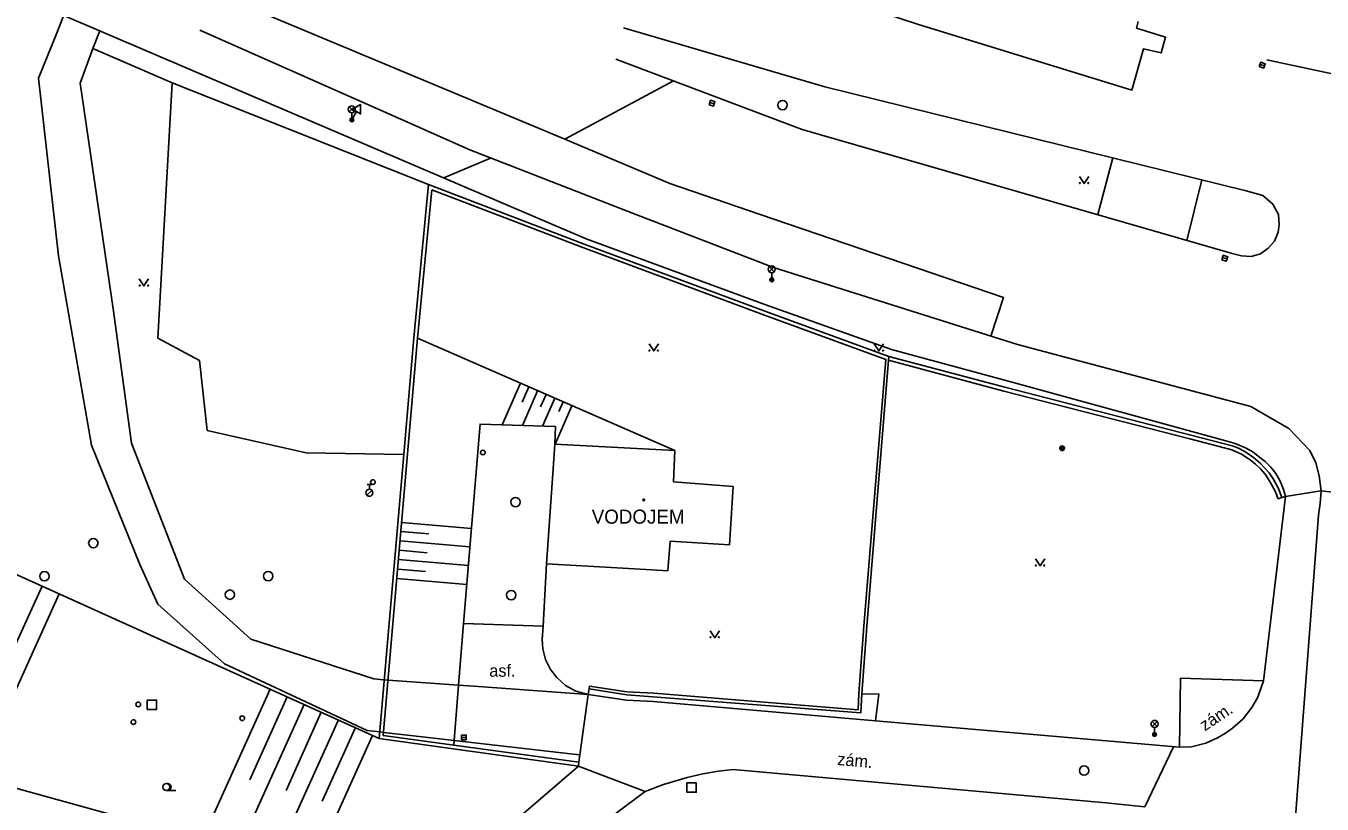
# Model space of a CAD drawing. Extents: x -602419 to -601554, y -1162937 to -1162362.
# Drawn here: x -602032.9 to -601963.7, y -1162448.9 to -1162407.3 of the extents above; entities that cross this region are included whole.
import ezdxf

# ---------------------------------------------------------------- set-up
doc = ezdxf.new("R2010")
doc.units = 0
doc.layers.add('Podklad', color=7, linetype='Continuous')

msp = doc.modelspace()

# ---------------------------------------------------------------- linework, layer by layer
at = {"layer": 'Podklad'}
for p, q in [((-601966.9783, -1162409.3796), (-601966.7417, -1162409.4604)), ((-602015.6024, -1162411.91), (-602015.3374, -1162411.645)), ((-602015.6024, -1162411.645), (-602015.3374, -1162411.91)), ((-602015.2154, -1162411.8992), (-602015.4699, -1162412.34)), ((-602015.4699, -1162411.965), (-602015.4699, -1162412.34)), ((-601996.3595, -1162411.4134), (-601996.1205, -1162411.4866)), ((-602015.5782, -1162412.2775), (-602015.3616, -1162412.4025)), ((-601993.1825, -1162420.45), (-601992.9175, -1162420.185)), ((-601993.1825, -1162420.185), (-601992.9175, -1162420.45)), ((-601968.979, -1162419.6916), (-601968.741, -1162419.7684)), ((-601993.05, -1162420.505), (-601993.05, -1162420.88)), ((-602014.659, -1162432.386), (-602014.394, -1162432.121)), ((-602014.655, -1162431.8125), (-602014.405, -1162431.8125)), ((-602014.53, -1162432.0625), (-602014.53, -1162431.8125)), ((-601972.7425, -1162444.72), (-601972.4775, -1162444.455)), ((-601972.7425, -1162444.455), (-601972.4775, -1162444.72)), ((-601972.61, -1162444.775), (-601972.61, -1162445.15)), ((-602009.605, -1162445.31), (-602009.355, -1162445.31)), ((-602025.37, -1162448.1475), (-602024.87, -1162448.1475))]:
    msp.add_line(p, q, dxfattribs=at)
for points in [[(-601981.359, -1162423.886), (-601980.675, -1162421.822), (-601993.665, -1162417.388), (-601998.487, -1162415.733), (-602004.099, -1162413.377), (-602022.511, -1162405.666), (-602036.956, -1162399.221), (-602052.146, -1162392.22), (-602072.492, -1162382.698), (-602084.592, -1162376.742), (-602104.849, -1162366.563), (-602105.932, -1162368.585)], [(-602002.95, -1162418.7), (-602040.4, -1162402.67), (-602062.69, -1162392.39), (-602086.01, -1162381.11), (-602086.4099, -1162381.89)], [(-601973.48, -1162407.09), (-601973.58, -1162407.44), (-601972.02, -1162407.93), (-601972.25, -1162408.76), (-601973.2, -1162408.55), (-601973.82, -1162410.75), (-601985.27, -1162407.23), (-601993.98, -1162404.37), (-601993.06, -1162401.37), (-601992.65, -1162401.49), (-601992.52, -1162401.17)], [(-602107.1599, -1162403.26), (-602014, -1162445.37)], [(-602030.84, -1162406.76), (-602031.24, -1162407.75), (-602032.2, -1162410.12), (-602031.13, -1162419.6), (-602029.36, -1162429.7), (-602026.79, -1162436.08), (-602025.82, -1162438.2), (-602022.27, -1162441.39), (-602014.65, -1162444.94), (-602013.98, -1162445.01), (-602013.97, -1162445.01), (-602013.78, -1162445.04), (-602012.33, -1162445.2), (-602010.01, -1162445.47), (-602003.8, -1162446.18), (-602003.29, -1162446.24)], [(-602028.93, -1162407.58), (-602029.29, -1162408.54), (-602029.98, -1162410.39), (-602028.21, -1162422.43), (-602027.23, -1162429.61), (-602024.4, -1162436.87), (-602020.86, -1162440.06), (-602014.3, -1162442.19), (-602013.78, -1162442.23), (-602013.73, -1162442.23), (-602013.53, -1162442.25), (-602009.77, -1162442.52), (-602008.7, -1162442.6), (-602002.85, -1162443.02)], [(-602023.58, -1162407.55), (-602014.1, -1162411.76)], [(-602000.9699, -1162407.42), (-601990.2199, -1162410.57), (-601967.71, -1162416.13)], [(-602012.7, -1162430.2), (-602017.91, -1162430.11), (-602023.19, -1162428.92), (-602023.61, -1162425.18), (-602025.83, -1162423.99), (-602025.06, -1162410.37), (-602029.29, -1162408.54)], [(-601968.4699, -1162419.4699), (-601991.43, -1162412.85), (-602001.38, -1162409.1)], [(-601943, -1162410.58), (-601947.67, -1162412.04), (-601949.61, -1162412.43), (-601951.69, -1162412.34), (-601957.12, -1162411.17), (-601966.61, -1162409.13)], [(-602025.06, -1162410.37), (-602011.37, -1162415.79)], [(-602004.099, -1162413.377), (-601998.294, -1162410.2631)], [(-602014.1, -1162411.76), (-602009.17, -1162413.95), (-602000.48, -1162417.32)], [(-602010.5574, -1162415.4438), (-602008.0558, -1162414.3821)], [(-601975.6428, -1162417.4018), (-601974.839, -1162414.3691)], [(-601976.62, -1162415.365), (-601976.37, -1162415.74), (-601976.12, -1162415.365)], [(-602014, -1162445.37), (-602012.7, -1162430.2), (-602012.16, -1162423.98), (-602011.37, -1162415.79)], [(-602011.96, -1162424), (-602011.2, -1162416.07)], [(-602011.37, -1162415.79), (-602003.06, -1162418.98)], [(-602011.2, -1162416.07), (-602003.13, -1162419.1599)], [(-601970.8787, -1162418.7754), (-601970.0799, -1162415.5446)], [(-601967.71, -1162416.13), (-601966.82, -1162416.38), (-601966.29, -1162416.85), (-601965.99, -1162417.4), (-601965.95, -1162417.93), (-601966.01, -1162418.34), (-601966.21, -1162418.81), (-601966.54, -1162419.2), (-601966.96, -1162419.49), (-601967.45, -1162419.63), (-601967.96, -1162419.6), (-601968.4699, -1162419.4699)], [(-602000.48, -1162417.32), (-601992.96, -1162420.23)], [(-601986.8, -1162424.98), (-601993.37, -1162422.58), (-602003.06, -1162418.98)], [(-602002.95, -1162418.7), (-601993.4099, -1162422.19), (-601986.6599, -1162424.6), (-601980.4699, -1162426.27), (-601968.81, -1162429.4699), (-601968.31, -1162429.62), (-601967.7199, -1162429.86), (-601967.37, -1162430.06), (-601966.98, -1162430.37)], [(-602003.13, -1162419.16), (-601993.44, -1162422.77), (-601986.96, -1162425.13), (-601988.13, -1162439.38), (-601988.39, -1162442.97), (-601988.44, -1162443.84), (-601999.34, -1162442.95), (-602000.78, -1162442.88)], [(-601979.92, -1162424.34), (-601992.96, -1162420.23)], [(-602026.82, -1162420.835), (-602026.57, -1162421.21), (-602026.32, -1162420.835)], [(-602010.03, -1162445.7199), (-602013.79, -1162445.2), (-602011.96, -1162424)], [(-601998.2199, -1162430), (-602011.96, -1162424)], [(-601999.6, -1162424.305), (-601999.35, -1162424.68), (-601999.1, -1162424.305)], [(-601987.58, -1162424.305), (-601987.33, -1162424.68), (-601987.08, -1162424.305)], [(-601979.92, -1162424.34), (-601967.4699, -1162427.65)], [(-601988.24, -1162442.98), (-601987.98, -1162439.39), (-601986.82, -1162425.17)], [(-601986.82, -1162425.17), (-601986.8, -1162424.98)], [(-601968.48, -1162429.96), (-601970.73, -1162429.37), (-601980.6599, -1162426.82), (-601986.82, -1162425.17)], [(-601986.8, -1162424.98), (-601980.61, -1162426.62), (-601970.68, -1162429.17), (-601968.4, -1162429.77)], [(-602006.4699, -1162426.4), (-602007.44, -1162428.62)], [(-602006.01, -1162426.6), (-602006.37, -1162427.4099)], [(-602005.55, -1162426.8), (-602006.36, -1162428.6599)], [(-602005.09, -1162427), (-602005.39, -1162427.67)], [(-602004.63, -1162427.2), (-602005.29, -1162428.7)], [(-602003.7199, -1162427.6), (-602004.62, -1162429.6599)], [(-602004.18, -1162427.4), (-602004.4099, -1162427.92)], [(-601967.4699, -1162427.65), (-601965.44, -1162428.81)], [(-602004.63, -1162429.66), (-602004.6, -1162428.72), (-602008.62, -1162428.58), (-602009.5, -1162439.23), (-602009.77, -1162442.52), (-602010.01, -1162445.47), (-602010.03, -1162445.72)], [(-601964.31, -1162430), (-601965.44, -1162428.81)], [(-602004.7199, -1162430.98), (-602004.63, -1162429.6599)], [(-602004.63, -1162429.6599), (-602000.26, -1162429.89)], [(-602000.26, -1162429.89), (-601998.2199, -1162430)], [(-601998.2199, -1162430), (-601998.3, -1162431.6599)], [(-601968.48, -1162429.96), (-601967.9699, -1162430.19), (-601967.5, -1162430.49), (-601967.2199, -1162430.7199), (-601966.95, -1162430.98), (-601966.71, -1162431.26), (-601966.45, -1162431.64), (-601966.17, -1162432.1599), (-601966.01, -1162432.57)], [(-601965.81, -1162432.51), (-601965.99, -1162432.02), (-601966.28, -1162431.5), (-601966.49, -1162431.19), (-601966.95, -1162430.68), (-601967.33, -1162430.36), (-601967.74, -1162430.08), (-601968.1, -1162429.89), (-601968.4, -1162429.77)], [(-601964.31, -1162430), (-601964, -1162430.65), (-601963.82, -1162431.35), (-601963.7199, -1162432.17), (-601963.76, -1162432.82), (-601963.86, -1162433.44)], [(-601966.98, -1162430.37), (-601966.7, -1162430.58), (-601966.4, -1162430.89), (-601966.13, -1162431.2199), (-601965.9, -1162431.63), (-601965.7199, -1162432.07), (-601965.62, -1162432.45)], [(-602005.07, -1162436.05), (-602004.7199, -1162430.98)], [(-601998.3, -1162431.6599), (-601995.11, -1162431.9099)], [(-601995.11, -1162431.9099), (-601995.3, -1162435.03)], [(-601956.3597, -1162432.9701), (-601963.7232, -1162432.1419), (-601963.74, -1162432.1399), (-601965.62, -1162432.45)], [(-601965.62, -1162432.45), (-601966.79, -1162442.29)], [(-601965.81, -1162432.51), (-601966.01, -1162432.57)], [(-601965.81, -1162432.51), (-601965.62, -1162432.45)], [(-601963.86, -1162433.44), (-601965.11, -1162449.78)], [(-602012.81, -1162433.83), (-602009.08, -1162434.15)], [(-602012.89, -1162434.82), (-602009.1599, -1162435.14)], [(-602012.85, -1162434.32), (-602011.36, -1162434.45)], [(-601998.4699, -1162434.83), (-601998.6, -1162436.42)], [(-601995.3, -1162435.03), (-601998.4699, -1162434.83)], [(-602012.94, -1162435.32), (-602011.44, -1162435.45)], [(-602012.98, -1162435.82), (-602009.24, -1162436.14)], [(-602005.3, -1162440.09), (-602005.26, -1162439.37), (-602005.07, -1162436.05)], [(-602001.92, -1162436.23), (-602005.07, -1162436.05)], [(-601999.4699, -1162436.37), (-602001.92, -1162436.23)], [(-601978.9699, -1162435.775), (-601978.7199, -1162436.15), (-601978.4699, -1162435.775)], [(-602013.07, -1162436.82), (-602009.32, -1162437.14)], [(-602013.02, -1162436.32), (-602011.53, -1162436.45)], [(-601998.6, -1162436.42), (-601999.4699, -1162436.37)], [(-602031.1, -1162437.64), (-602035.42, -1162447.21)], [(-602032.01, -1162437.23), (-602033.74, -1162441.06)], [(-602005.26, -1162439.37), (-602009.5, -1162439.23)], [(-601996.34, -1162439.615), (-601996.09, -1162439.99), (-601995.84, -1162439.615)], [(-602005.3, -1162440.09), (-602005.27, -1162440.59), (-602005.13, -1162441.1599), (-602004.86, -1162441.69), (-602004.53, -1162442.12), (-602004.06, -1162442.54), (-602003.5, -1162442.84), (-602002.85, -1162443.02)], [(-601971.28, -1162445.84), (-601971.2199, -1162442.14), (-601966.79, -1162442.29)], [(-601971.28, -1162445.84), (-601970.64, -1162445.81), (-601969.87, -1162445.62), (-601969.24, -1162445.34), (-601968.82, -1162445.09), (-601968.44, -1162444.82), (-601967.87, -1162444.32), (-601967.4099, -1162443.71), (-601967.12, -1162443.2), (-601966.95, -1162442.76), (-601966.79, -1162442.29)], [(-602019.83, -1162442.73), (-602024.9699, -1162454.12)], [(-602018.92, -1162443.15), (-602020.92, -1162447.58)], [(-602003.34, -1162446.64), (-602003.29, -1162446.24), (-602002.85, -1162443.02)], [(-602002.85, -1162443.02), (-602002.8, -1162442.7199)], [(-602000.8, -1162443.33), (-602002.85, -1162443.02)], [(-602002.8, -1162442.7199), (-602002.78, -1162442.57)], [(-602002.8, -1162442.7199), (-602000.79, -1162443.03)], [(-602002.78, -1162442.57), (-602000.78, -1162442.88)], [(-601988.24, -1162442.98), (-601988.3, -1162444), (-602000.79, -1162443.03)], [(-601987.5, -1162444.43), (-601987.33, -1162443.01), (-601988.24, -1162442.98)], [(-602018.01, -1162443.56), (-602022.87, -1162454.32)], [(-602000.8, -1162443.33), (-601999.37, -1162443.4), (-601987.5, -1162444.43)], [(-602016.18, -1162444.38), (-602020.77, -1162454.52)], [(-602017.1, -1162443.9699), (-602018.98, -1162448.15)], [(-601971.28, -1162445.84), (-601987.5, -1162444.43)], [(-602014.36, -1162445.21), (-602018.6599, -1162454.7199)], [(-602015.27, -1162444.79), (-602017.05, -1162448.7199)], [(-602003.37, -1162446.84), (-602010.05, -1162445.92), (-602014, -1162445.37)], [(-602003.34, -1162446.64), (-602010.03, -1162445.7199)], [(-601973.13, -1162449.02), (-601971.593, -1162445.8128)], [(-602003.34, -1162446.64), (-602003.37, -1162446.84)], [(-602003.37, -1162446.84), (-602005.15, -1162448.38)], [(-601999.81, -1162448.2), (-602002.16, -1162447.3099), (-602003.37, -1162446.84)], [(-601999.81, -1162448.2), (-601998.82, -1162447.82), (-601997.56, -1162447.45), (-601996.73, -1162447.26), (-601995.89, -1162447.12), (-601995.11, -1162447.03)], [(-601995.11, -1162447.03), (-601975.2, -1162448.8), (-601973.13, -1162449.02)], [(-602009.8073, -1162454.5516), (-602033.93, -1162447.87)], [(-602005.15, -1162448.38), (-602006.53, -1162449.56), (-602010.43, -1162455.5)], [(-602002.9699, -1162450.57), (-601999.81, -1162448.2)]]:
    msp.add_lwpolyline(points, dxfattribs=at)
for points in [[(-601967.0187, -1162409.4978), (-601966.7822, -1162409.5787), (-601966.7013, -1162409.3422), (-601966.9378, -1162409.2613)], [(-601996.3961, -1162411.533), (-601996.157, -1162411.6061), (-601996.0839, -1162411.367), (-601996.323, -1162411.2939)], [(-602015.4319, -1162411.7742), (-602014.9989, -1162412.0242), (-602014.9989, -1162411.5242)], [(-601969.0173, -1162419.8106), (-601968.7794, -1162419.8873), (-601968.7027, -1162419.6494), (-601968.9406, -1162419.5727)], [(-602026.39, -1162443.82), (-602025.89, -1162443.82), (-602025.89, -1162443.32), (-602026.39, -1162443.32)], [(-602009.605, -1162445.435), (-602009.355, -1162445.435), (-602009.355, -1162445.185), (-602009.605, -1162445.185)], [(-601997.58, -1162448.24), (-601997.08, -1162448.24), (-601997.08, -1162447.74), (-601997.58, -1162447.74)]]:
    msp.add_lwpolyline(points, close=True, dxfattribs=at)
for centre, radius in [((-601992.4699, -1162411.55), 0.25), ((-602015.4699, -1162411.7775), 0.1875), ((-602015.4699, -1162412.34), 0.1), ((-602015.4699, -1162412.34), 0.0723), ((-602015.4699, -1162412.34), 0.0438), ((-601976.5951, -1162415.7149), 0.025), ((-601976.1454, -1162415.7149), 0.025), ((-601993.05, -1162420.3175), 0.1875), ((-601993.05, -1162420.88), 0.1), ((-601993.05, -1162420.88), 0.0723), ((-601993.05, -1162420.88), 0.0438), ((-602026.7951, -1162421.1849), 0.025), ((-602026.3454, -1162421.1849), 0.025), ((-601999.5751, -1162424.6549), 0.025), ((-601999.1254, -1162424.6549), 0.025), ((-601987.5551, -1162424.6549), 0.025), ((-601987.1054, -1162424.6549), 0.025), ((-602008.4699, -1162430.1), 0.125), ((-601977.55, -1162429.87), 0.125), ((-601977.55, -1162429.87), 0.1), ((-601977.55, -1162429.87), 0.075), ((-601977.55, -1162429.87), 0.05), ((-601977.55, -1162429.87), 0.025), ((-602014.53, -1162432.25), 0.1875), ((-602014.34, -1162431.68), 0.125), ((-602006.73, -1162432.75), 0.25), ((-601999.88, -1162432.63), 0.045), ((-601999.88, -1162432.63), 0.0199), ((-602029.27, -1162434.94), 0.25), ((-601978.945, -1162436.1249), 0.025), ((-601978.4953, -1162436.1249), 0.025), ((-602031.88, -1162436.71), 0.25), ((-602019.93, -1162436.7), 0.25), ((-602021.98, -1162437.69), 0.25), ((-602006.96, -1162437.71), 0.25), ((-601996.3151, -1162439.9649), 0.025), ((-601995.8654, -1162439.9649), 0.025), ((-602026.87, -1162443.55), 0.125), ((-602027.13, -1162444.49), 0.125), ((-602021.32, -1162444.29), 0.125), ((-601972.61, -1162444.5875), 0.1875), ((-601972.61, -1162445.15), 0.1), ((-601972.61, -1162445.15), 0.0723), ((-601972.61, -1162445.15), 0.0438), ((-601976.37, -1162447.08), 0.25), ((-602025.37, -1162447.9598), 0.1875)]:
    msp.add_circle(centre, radius, dxfattribs=at)
msp.add_arc((-602025.3075, -1162447.9598), 0.1875, 260.405931, 99.594069, dxfattribs=at)

# ---------------------------------------------------------------- texts
for s, height, p in [('VODOJEM', 0.75, (-602002.6599, -1162433.9)), ('asf.', 0.65, (-602008.13, -1162442.07))]:
    msp.add_text(s, height=height, dxfattribs=at).set_placement(p)
for rotation, p in [(33.51, (-601970.13, -1162445.13)), (354.92, (-601989.81, -1162446.76))]:
    msp.add_text(' zám.', height=0.65, rotation=rotation, dxfattribs=at).set_placement(p)

doc.saveas('drawing.dxf')
